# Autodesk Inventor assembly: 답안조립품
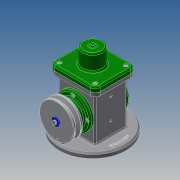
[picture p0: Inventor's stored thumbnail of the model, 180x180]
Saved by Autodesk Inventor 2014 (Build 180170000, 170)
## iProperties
Created: 2019-08
Part Number: 답안조립품
Document SubType Name: Assembly
Designer: kb542-11
Author: kb542-11
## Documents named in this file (18)
- C:\Users\kb542-11\Desktop\490804V1009\답안조립품.iam
- C:\Users\kb542-11\Desktop\490804V1009\본체.ipt
- C:\Users\kb542-11\Desktop\490804V1009\E-링.ipt
- C:\Users\kb542-11\Desktop\490804V1009\V-벨트풀리.ipt
- C:\Users\kb542-11\Desktop\490804V1009\덮개.ipt
- C:\Users\kb542-11\Desktop\490804V1009\뒤커버.ipt
- C:\Users\kb542-11\Desktop\490804V1009\링크.ipt
- C:\Users\kb542-11\Desktop\490804V1009\베어링 17 x 40 x 12.ipt
- C:\Users\kb542-11\Desktop\490804V1009\볼트 M4 x 8.ipt
- C:\Users\kb542-11\Desktop\490804V1009\볼트 M4 x 10.ipt
- C:\Users\kb542-11\Desktop\490804V1009\슬라이더.ipt
- C:\Users\kb542-11\Desktop\490804V1009\앞커버.ipt
- C:\Users\kb542-11\Desktop\490804V1009\오일 실 17 30 8.ipt
- C:\Users\kb542-11\Desktop\490804V1009\와셔 4x16.ipt
- C:\Users\kb542-11\Desktop\490804V1009\클레비스 핀 6 x 22.ipt
- 클레비스 핀 6 x 22.ipt
- C:\Users\kb542-11\Desktop\490804V1009\키 4 x 4 x 12.ipt
- C:\Users\kb542-11\Desktop\490804V1009\편심축.ipt
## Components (2 placed, 2 different names)
1. E-링:1 — 각도:3
2. V-벨트풀리:1 — 각도:2
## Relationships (2: Angle 2)
- 각도:2 [Angle]: V-벨트풀리:1
- 각도:3 [Angle]: E-링:1
